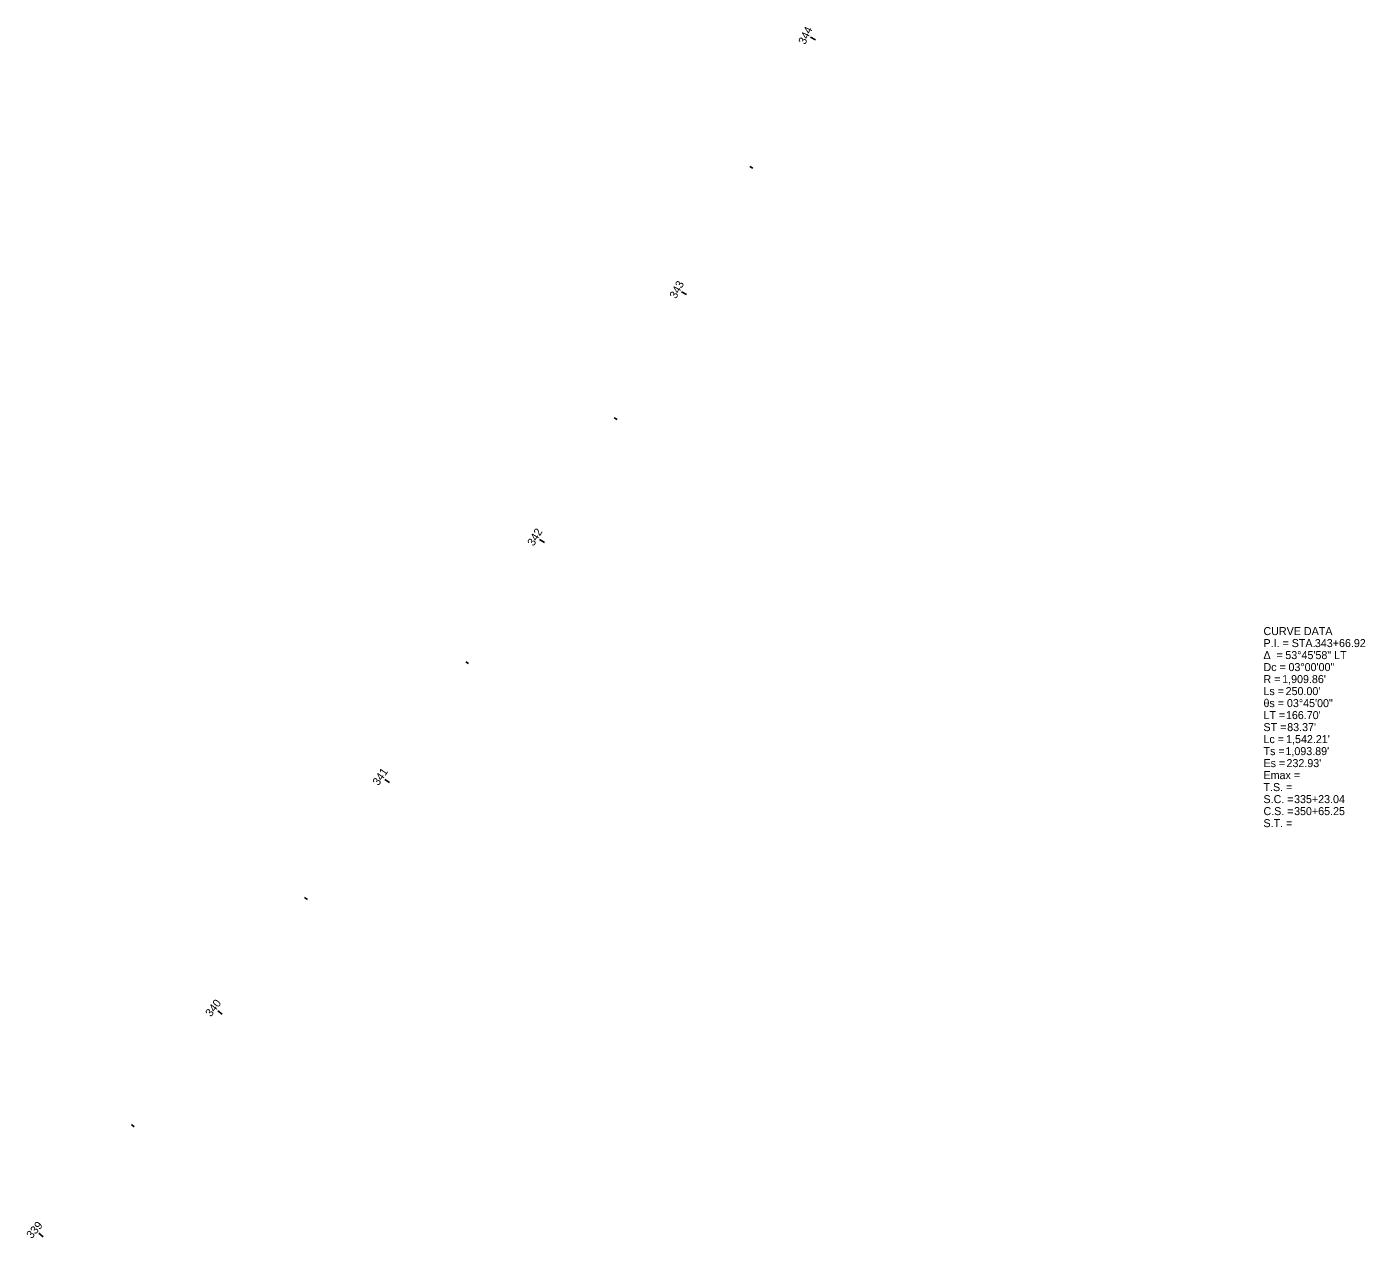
# Model space of a CAD drawing. Extents: x 1380777 to 1381940, y 503546 to 507267.
# Drawn here: x 1381298 to 1381766.5, y 503972.6 to 504396.5 of the extents above; entities that cross this region are included whole.
import ezdxf

# ---------------------------------------------------------------- set-up
doc = ezdxf.new("R2010")
doc.units = 0
doc.layers.add('GE_X_Alignment_100_Curve_Data', color=7, linetype='Continuous')
doc.layers.add('GE_X_Alignment_500_Stations', color=7, linetype='Continuous')

msp = doc.modelspace()

# ---------------------------------------------------------------- linework, layer by layer
at = {"layer": 'GE_X_Alignment_500_Stations'}
for p, q in [((1381574.08, 504391.99), (1381572.27, 504392.84)), ((1381552.1, 504347.08), (1381551.03, 504347.62)), ((1381528.95, 504302.77), (1381527.19, 504303.72)), ((1381504.64, 504259.07), (1381503.6, 504259.67)), ((1381479.21, 504216.03), (1381477.5, 504217.07)), ((1381452.65, 504173.66), (1381451.64, 504174.31)), ((1381424.99, 504132.01), (1381423.34, 504133.14)), ((1381396.26, 504091.1), (1381395.28, 504091.8)), ((1381366.46, 504050.95), (1381364.87, 504052.16)), ((1381335.62, 504011.59), (1381334.69, 504012.34)), ((1381303.76, 503973.06), (1381302.24, 503974.35))]:
    msp.add_line(p, q, dxfattribs=at)

# ---------------------------------------------------------------- texts
at = {"layer": 'GE_X_Alignment_100_Curve_Data'}
for s, p in [('CURVE DATA', (1381730.85, 504183.64)), ('P.I. = STA. ', (1381730.85, 504179.44)), ('343+66.92', (1381748.84, 504179.44)), ('Δ  = ', (1381730.85, 504175.24)), ('53°45\'58" LT', (1381738.49, 504175.24)), ('Dc = ', (1381730.85, 504171.04)), ('03°00\'00"', (1381739.59, 504171.04)), ('R = ', (1381730.85, 504166.84)), ("1,909.86'", (1381737.39, 504166.84)), ('θs = ', (1381730.85, 504158.44)), ('Ls = ', (1381730.85, 504162.64)), ("250.00'", (1381738.59, 504162.64)), ('03°45\'00"', (1381739.06, 504158.44)), ('LT = ', (1381730.85, 504154.24)), ("166.70'", (1381738.7, 504154.24)), ('ST = ', (1381730.85, 504150.04)), ("83.37'", (1381739.15, 504150.04)), ('Lc = ', (1381730.85, 504145.84)), ("1,542.21'", (1381738.76, 504145.84)), ('Ts = ', (1381730.85, 504141.64)), ("1,093.89'", (1381738.53, 504141.64)), ('Es = ', (1381730.85, 504137.44)), ("232.93'", (1381738.9, 504137.44)), ('Emax = ', (1381730.85, 504133.24)), ('T.S. = ', (1381730.85, 504129.04)), ('S.C. = ', (1381730.85, 504124.84)), ('C.S. = ', (1381730.85, 504120.64)), ('335+23.04', (1381741.55, 504124.84)), ('350+65.25', (1381741.55, 504120.64)), ('S.T. = ', (1381730.85, 504116.44))]:
    msp.add_text(s, height=2.8, dxfattribs=at).set_placement(p)
at = {"layer": 'GE_X_Alignment_500_Stations'}
for s, rotation, p in [('344', 64.6677, (1381570.42, 504390.09)), ('343', 61.6677, (1381525.23, 504301.14)), ('342', 58.6677, (1381475.4, 504214.58)), ('341', 55.6677, (1381421.11, 504130.76)), ('340', 52.6677, (1381362.49, 504049.86)), ('339', 49.6677, (1381299.77, 503972.22))]:
    msp.add_text(s, height=2.8, rotation=rotation, dxfattribs=at).set_placement(p)

doc.saveas('drawing.dxf')
